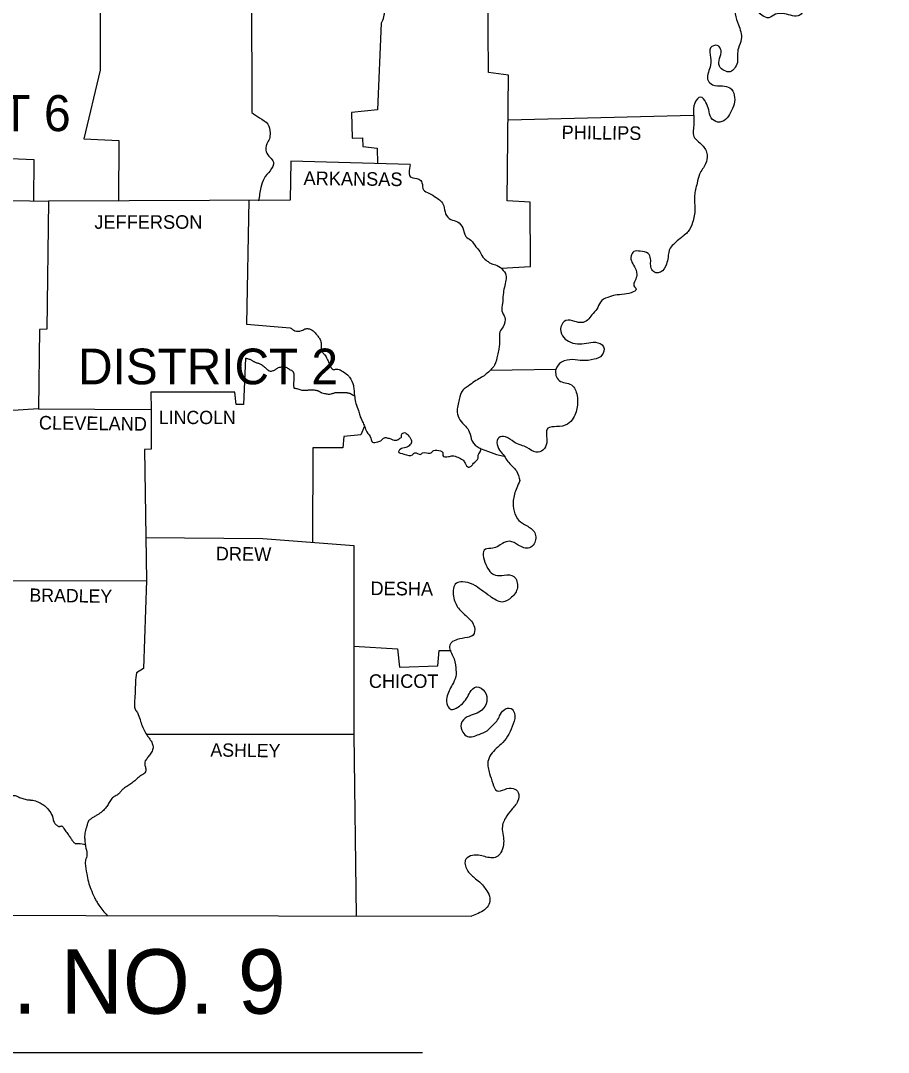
# Model space of a CAD drawing. Extents: x 0 to 3171, y 0 to 2059.
# Drawn here: x 2812.1 to 3086.8, y 1309.2 to 1635.7 of the extents above; entities that cross this region are included whole.
import ezdxf

# ---------------------------------------------------------------- set-up
doc = ezdxf.new("R2010")
doc.units = 0
doc.layers.add('Default', color=7, linetype='Continuous')
doc.layers.add('Level 1', color=7, linetype='Continuous')

msp = doc.modelspace()

# ---------------------------------------------------------------- linework, layer by layer
at = {"layer": 'Default'}
msp.add_line((2620.8, 1309.22), (2939.39, 1309.22), dxfattribs=at)
at = {"layer": 'Level 1'}
msp.add_line((2960.87, 1525.15), (2981.61, 1525.46), dxfattribs=at)
for points in [[(2870.87, 1663.24), (2871.07, 1645.34), (2885.17, 1645.04), (2885.27, 1606.64)], [(2831.37, 1658.64), (2837.17, 1658.24), (2837.27, 1620.04), (2832.07, 1598.34), (2843.17, 1597.84), (2843.07, 1578.73)], [(2964.24, 1557.34), (2973.57, 1557.94), (2973.47, 1578.24), (2966.17, 1578.74), (2966.57, 1618.44), (2960.27, 1619.34), (2960.07, 1646.04), (3045.85, 1646.64)], [(2753.47, 1633.68), (2765.37, 1632.94), (2764.97, 1620.44), (2778.07, 1619.94), (2778.27, 1609.04), (2784.47, 1608.54), (2784.47, 1606.64), (2790.27, 1606.24), (2790.47, 1599.24), (2803.67, 1599.24), (2804.07, 1592.34), (2816.27, 1591.74), (2816.17, 1578.72)], [(2926.27, 1634.94), (2925.07, 1607.54), (2916.87, 1606.64), (2917.07, 1598.54), (2920.37, 1598.64), (2920.47, 1595.84), (2924.97, 1595.34), (2925.12, 1590.51)], [(2966.43, 1604.33), (3025.18, 1605.79)], [(2935.47, 1590.24), (2897.67, 1591.24), (2897.47, 1578.94), (2820.97, 1578.64)], [(2763.37, 1565.44), (2768.97, 1566.24), (2769.37, 1569.64), (2772.67, 1570.24), (2772.87, 1572.24), (2796.17, 1572.94), (2797.07, 1579.04), (2820.97, 1578.64)], [(2820.97, 1578.64), (2820.37, 1538.04), (2818.07, 1537.94), (2817.77, 1512.84)], [(2884.4, 1578.89), (2883.57, 1539.64), (2897.47, 1538.54)], [(2883.27, 1528.94), (2882.67, 1514.24), (2880.37, 1514.24), (2879.97, 1518.14), (2853.37, 1518.14), (2853.4, 1512.64)], [(2817.77, 1512.84), (2803.15, 1511.94)], [(2817.77, 1512.84), (2853.4, 1512.64)], [(2853.4, 1512.64), (2853.47, 1500.14), (2851.37, 1500.04), (2851.97, 1458.54)], [(2920.97, 1507.34), (2919.77, 1504.64), (2914.47, 1504.14), (2914.17, 1500.54), (2904.67, 1500.54), (2904.57, 1470.64)], [(2957.97, 1500.24), (2960.21, 1499.37), (2962.77, 1498.47), (2965.21, 1497.85)], [(2851.67, 1472.14), (2888.77, 1471.84), (2917.57, 1469.64)], [(2917.57, 1469.64), (2917.57, 1409.85), (2918.37, 1352.41)], [(2806.77, 1458.44), (2851.97, 1458.54)], [(2851.97, 1458.54), (2850.97, 1430.74), (2848.77, 1429.34)], [(2917.57, 1437.77), (2931.47, 1436.94), (2932.07, 1431.14), (2944.17, 1431.54), (2944.67, 1436.44), (2948.41, 1436.44)], [(2588.17, 1433.84), (2588.37, 1352.95), (2954.87, 1352.35)], [(2851.92, 1409.95), (2917.57, 1409.95)]]:
    msp.add_lwpolyline(points, dxfattribs=at)
for points in [[(3082.47, 1721.54), (3082.87, 1718.64), (3081.17, 1715.54), (3080.57, 1712.44), (3080.87, 1709.34), (3077.67, 1707.64), (3074.87, 1705.64), (3076.47, 1703.24), (3079.47, 1701.04), (3082.47, 1699.34), (3084.37, 1697.64), (3084.87, 1693.54), (3085.37, 1690.94), (3086.37, 1687.34), (3086.77, 1684.84), (3084.97, 1681.84), (3082.87, 1681.24), (3080.67, 1681.94), (3078.07, 1682.14), (3075.97, 1680.14), (3074.47, 1677.34), (3072.97, 1674.54), (3071.87, 1672.14), (3070.77, 1669.54), (3068.57, 1666.54), (3065.87, 1666.04), (3062.67, 1665.24), (3060.77, 1663.04), (3061.07, 1659.34), (3062.87, 1656.84), (3064.27, 1653.74), (3065.27, 1651.04), (3064.77, 1647.64), (3063.37, 1645.14), (3061.57, 1643.64), (3060.77, 1640.44), (3059.47, 1638.04), (3058.27, 1637.24), (3055.87, 1637.44), (3053.27, 1637.94), (3051.07, 1637.74), (3048.97, 1636.64), (3046.87, 1637.34), (3044.67, 1639.74), (3042.87, 1641.54), (3040.87, 1642.24), (3038.77, 1641.14), (3038.37, 1637.84), (3039.37, 1634.44), (3040.27, 1629.84), (3039.37, 1627.04), (3039.07, 1622.44)], [(2925.17, 1644.54), (2925.05, 1644.3), (2924.96, 1644.05), (2924.83, 1643.54), (2924.77, 1643.04), (2924.76, 1642.79), (2924.77, 1642.54), (2924.85, 1642), (2925.02, 1641.47), (2925.27, 1640.95), (2925.41, 1640.69), (2925.57, 1640.44), (2925.71, 1640.3), (2925.89, 1640.2), (2926.3, 1640.1), (2926.7, 1640), (2926.86, 1639.9), (2926.92, 1639.83), (2926.97, 1639.74), (2927.02, 1639.62), (2927.06, 1639.49), (2927.22, 1638.74), (2927.23, 1638.24), (2927.21, 1637.99), (2927.17, 1637.74), (2926.97, 1636.73), (2926.84, 1636.23), (2926.76, 1635.99), (2926.67, 1635.74), (2926.49, 1635.33), (2926.27, 1634.94)], [(3039.07, 1622.44), (3036.77, 1619.54), (3033.37, 1621.34), (3033.37, 1623.74), (3033.87, 1626.24), (3032.67, 1627.84), (3030.57, 1627.14), (3030.57, 1624.04), (3030.37, 1621.04), (3029.77, 1616.74), (3031.17, 1615.44), (3034.37, 1615.04), (3036.67, 1614.44), (3038.07, 1612.14), (3037.97, 1609.34), (3036.87, 1606.64), (3035.27, 1604.44), (3032.77, 1603.64), (3030.77, 1604.94), (3029.97, 1607.54), (3029.07, 1609.84), (3027.37, 1611.54), (3025.57, 1609.64), (3025.17, 1606.14), (3025.27, 1603.14), (3025.27, 1599.04), (3027.87, 1596.34), (3029.47, 1593.24), (3028.97, 1590.44), (3027.07, 1587.14), (3026.27, 1584.24), (3025.47, 1580.34), (3025.57, 1576.04), (3024.87, 1571.84), (3023.47, 1569.04), (3020.87, 1566.74), (3019.17, 1565.24), (3017.77, 1563.74), (3017.07, 1560.74), (3016.57, 1558.64), (3014.67, 1556.14), (3013.17, 1555.94), (3011.97, 1556.94), (3011.57, 1558.64), (3011.57, 1560.34), (3010.77, 1562.04), (3008.27, 1562.74), (3006.27, 1562.64), (3005.37, 1561.24), (3006.67, 1557.34), (3007.17, 1554.84), (3006.47, 1551.44), (3006.87, 1551.04), (3003.27, 1549.14), (3000.37, 1548.84), (2997.97, 1548.14), (2995.67, 1546.64), (2994.57, 1544.44), (2992.97, 1542.64), (2991.57, 1540.94), (2989.67, 1540.14), (2987.57, 1540.54), (2984.77, 1540.84), (2983.17, 1538.84), (2983.67, 1535.94), (2985.57, 1534.24), (2988.37, 1533.44), (2991.27, 1533.64), (2994.07, 1533.94), (2996.67, 1532.54), (2996.17, 1529.84), (2993.67, 1528.54), (2989.97, 1528.14), (2986.97, 1528.44), (2983.37, 1527.64), (2981.57, 1525.34), (2982.57, 1521.84), (2986.47, 1520.44), (2988.27, 1517.14), (2988.37, 1514.04), (2987.07, 1509.94), (2985.27, 1508.04), (2981.77, 1507.24), (2979.07, 1506.74), (2978.67, 1502.14), (2977.47, 1499.84), (2975.37, 1499.14), (2972.37, 1500.64), (2970.57, 1501.34), (2968.37, 1502.34), (2965.57, 1504.04), (2963.47, 1503.74), (2964.07, 1499.34), (2964.27, 1499.14), (2966.67, 1495.84), (2969.07, 1493.24), (2970.17, 1490.14)], [(2885.27, 1606.64), (2887.77, 1604.94), (2890.37, 1602.94), (2891.07, 1600.24), (2890.87, 1598.34), (2890.07, 1596.74), (2889.87, 1594.24), (2891.07, 1592.44), (2892.17, 1590.94), (2891.07, 1588.24), (2889.17, 1585.74), (2888.17, 1582.94), (2887.47, 1578.74)], [(2935.47, 1590.24), (2935.77, 1586.14), (2938.17, 1585.54), (2939.17, 1584.44), (2939.67, 1582.14), (2941.37, 1581.14), (2943.67, 1579.74), (2945.07, 1578.74), (2946.07, 1577.14), (2946.67, 1574.54), (2948.27, 1572.84), (2950.47, 1572.04), (2952.07, 1570.14), (2953.07, 1567.44), (2954.67, 1566.24), (2956.27, 1564.14), (2957.07, 1563.24), (2958.47, 1560.84), (2959.87, 1559.64), (2960.87, 1558.94), (2962.47, 1558.44), (2964.47, 1557.14), (2965.77, 1555.14), (2965.77, 1553.64), (2965.27, 1551.34), (2964.87, 1548.94), (2964.67, 1546.24), (2964.47, 1543.84), (2965.37, 1541.84), (2964.87, 1538.84), (2963.87, 1537.24), (2963.77, 1535.04), (2963.47, 1531.74), (2963.07, 1529.84), (2962.17, 1526.74), (2960.87, 1525.14)], [(2897.47, 1538.54), (2898.97, 1537.54), (2901.07, 1537.64), (2902.47, 1538.24), (2903.57, 1538.14), (2905.07, 1537.24), (2906.07, 1536.04), (2906.77, 1535.14), (2907.27, 1533.74), (2907.27, 1532.44), (2907.77, 1530.64), (2908.37, 1529.94), (2909.17, 1528.64), (2909.67, 1527.44), (2909.97, 1526.64), (2911.07, 1525.34), (2912.07, 1525.44), (2912.97, 1525.34), (2914.17, 1524.64), (2915.97, 1523.24), (2916.27, 1522.84), (2917.47, 1520.24), (2917.67, 1518.64), (2917.87, 1516.54), (2918.27, 1514.54), (2919.07, 1512.34), (2919.47, 1510.84), (2920.37, 1508.74), (2920.97, 1507.34), (2921.77, 1505.54), (2922.97, 1503.54), (2923.47, 1502.34), (2925.17, 1502.44), (2926.37, 1502.94), (2927.27, 1503.74), (2928.37, 1503.64), (2929.57, 1503.24), (2931.17, 1502.94), (2932.17, 1503.54), (2932.67, 1503.94), (2932.77, 1504.84), (2933.67, 1505.34), (2934.67, 1504.64), (2935.77, 1503.04), (2935.77, 1502.04), (2935.37, 1501.44), (2934.07, 1500.64), (2932.27, 1500.04), (2931.77, 1499.34), (2933.47, 1498.54), (2936.17, 1498.34), (2936.87, 1498.94), (2938.67, 1498.44), (2939.37, 1498.94), (2941.77, 1498.84), (2942.87, 1499.64), (2945.07, 1499.54), (2945.77, 1499.04), (2945.77, 1498.14), (2947.57, 1497.74), (2948.87, 1498.04), (2950.57, 1497.54), (2952.07, 1496.74), (2952.87, 1495.64), (2953.87, 1494.44), (2954.77, 1494.74), (2955.47, 1495.64), (2956.97, 1497.24), (2956.97, 1498.24), (2957.37, 1498.94), (2957.97, 1500.24)], [(2883.27, 1528.94), (2883.73, 1528.85), (2884.19, 1528.71), (2885.07, 1528.34), (2885.4, 1528.17), (2885.72, 1527.99), (2886.04, 1527.81), (2886.37, 1527.64), (2886.79, 1527.48), (2887.23, 1527.36), (2887.66, 1527.23), (2888.07, 1527.04), (2888.63, 1526.66), (2889.17, 1526.24), (2889.55, 1525.92), (2889.91, 1525.58), (2890.28, 1525.24), (2890.47, 1525.09), (2890.67, 1524.94), (2891.08, 1524.8), (2891.55, 1524.83), (2892.03, 1524.97), (2892.47, 1525.14), (2892.8, 1525.33), (2893.1, 1525.56), (2893.42, 1525.78), (2893.77, 1525.94), (2895.07, 1526.14), (2896.07, 1526.04), (2897.17, 1525.44), (2897.82, 1525.07), (2898.12, 1524.85), (2898.25, 1524.71), (2898.31, 1524.63), (2898.37, 1524.54), (2898.57, 1523.9), (2898.57, 1523.57), (2898.57, 1523.24), (2898.57, 1521.74), (2898.57, 1519.64), (2898.64, 1519.5), (2898.83, 1519.42), (2899.27, 1519.34), (2900.51, 1518.96), (2901.77, 1518.74), (2902.19, 1518.75), (2902.62, 1518.78), (2903.04, 1518.82), (2903.47, 1518.84), (2904.27, 1518.86), (2905.07, 1518.84), (2905.73, 1518.74), (2906.05, 1518.65), (2906.37, 1518.54), (2906.65, 1518.4), (2906.92, 1518.23), (2907.19, 1518.07), (2907.47, 1517.94), (2908.27, 1517.74), (2909.47, 1517.54), (2910.47, 1517.64), (2910.9, 1517.75), (2911.32, 1517.88), (2911.74, 1517.99), (2912.17, 1518.04), (2913.17, 1518.04), (2914.77, 1518.04), (2915.27, 1518.01), (2915.52, 1517.98), (2915.77, 1517.94), (2916.84, 1517.55), (2917.35, 1517.24), (2917.83, 1516.91)], [(2960.87, 1525.14), (2958.07, 1522.84), (2956.27, 1521.84), (2954.37, 1520.44), (2952.07, 1518.74), (2950.97, 1515.84), (2950.37, 1511.84), (2951.17, 1509.44), (2952.97, 1507.34), (2954.17, 1505.64), (2955.07, 1502.64), (2957.27, 1500.54), (2957.97, 1500.24)], [(2970.17, 1490.14), (2969.17, 1487.84), (2968.07, 1483.84), (2968.37, 1480.44), (2969.87, 1477.54), (2972.27, 1475.94), (2974.87, 1473.64), (2974.67, 1470.14), (2973.17, 1468.84), (2969.67, 1469.74), (2966.97, 1470.94), (2964.67, 1470.24), (2961.57, 1468.74), (2959.27, 1468.44), (2959.37, 1463.64), (2962.47, 1460.24), (2965.17, 1460.24), (2968.27, 1459.84), (2969.37, 1456.24), (2967.57, 1453.24), (2964.57, 1451.74), (2960.77, 1453.54), (2958.07, 1455.44), (2955.37, 1457.24), (2951.97, 1458.14), (2950.07, 1457.74), (2949.17, 1453.54), (2950.77, 1449.74), (2953.37, 1447.14), (2955.77, 1443.74), (2955.37, 1441.24), (2953.57, 1440.54), (2950.37, 1439.84), (2948.47, 1438.84), (2947.97, 1438.04), (2948.97, 1434.64), (2949.87, 1430.94), (2949.87, 1428.15), (2948.77, 1425.55), (2947.07, 1421.55), (2947.27, 1418.95), (2948.47, 1417.75), (2949.97, 1418.15), (2951.97, 1419.55), (2953.27, 1421.15), (2954.37, 1423.15), (2956.47, 1424.85), (2959.07, 1423.35), (2959.67, 1420.25), (2958.17, 1417.55), (2956.07, 1416.35), (2953.47, 1415.35), (2951.57, 1413.15), (2952.07, 1410.55), (2953.57, 1409.15), (2957.27, 1409.85), (2959.77, 1410.95), (2961.17, 1412.35), (2962.87, 1414.05), (2963.77, 1415.75), (2965.07, 1417.55), (2967.37, 1418.05), (2968.47, 1416.55), (2968.07, 1413.15), (2966.67, 1409.95), (2964.77, 1407.25), (2962.67, 1405.35), (2960.07, 1401.25), (2960.57, 1397.45), (2961.57, 1394.35), (2962.97, 1391.95), (2965.37, 1392.45), (2968.07, 1392.75), (2969.67, 1391.45), (2969.47, 1388.65), (2967.47, 1385.95), (2965.57, 1383.35), (2964.57, 1379.75), (2964.97, 1377.25), (2964.97, 1374.95), (2964.17, 1372.45), (2962.77, 1371.05), (2959.07, 1371.15), (2955.17, 1371.55), (2953.07, 1370.35), (2953.47, 1366.95), (2955.77, 1364.45), (2957.37, 1363.15), (2959.67, 1360.35), (2960.67, 1358.05), (2960.37, 1356.05), (2958.97, 1354.35), (2954.87, 1352.35)], [(2848.77, 1429.34), (2848.47, 1426.25), (2848.37, 1423.35), (2848.17, 1420.55), (2848.11, 1419.49), (2848.12, 1418.97), (2848.17, 1418.45), (2848.37, 1417.84), (2848.71, 1417.28), (2849.08, 1416.73), (2849.37, 1416.15), (2850.07, 1413.95), (2850.77, 1412.05), (2852.17, 1409.55), (2852.48, 1409.06), (2852.82, 1408.6), (2853.15, 1408.13), (2853.47, 1407.65), (2853.98, 1406.3), (2854.02, 1405.6), (2853.87, 1404.95), (2853.07, 1403.55), (2852.7, 1403.01), (2852.32, 1402.49), (2851.93, 1401.97), (2851.57, 1401.45), (2851.4, 1400.53), (2851.62, 1399.49), (2851.78, 1398.47), (2851.47, 1397.65), (2851.26, 1397.47), (2851.04, 1397.31), (2850.58, 1397.03), (2850.11, 1396.76), (2849.67, 1396.45), (2848.54, 1395.43), (2847.97, 1394.92), (2847.37, 1394.45), (2846.07, 1393.55), (2844.67, 1392.65), (2844.26, 1392.29), (2843.9, 1391.87), (2843.55, 1391.44), (2843.17, 1391.05), (2842.64, 1390.65), (2842.05, 1390.32), (2841.48, 1389.97), (2840.97, 1389.55), (2840.52, 1388.96), (2840.15, 1388.31), (2839.79, 1387.66), (2839.37, 1387.05), (2838.95, 1386.54), (2838.53, 1386.04), (2837.57, 1385.15), (2836.07, 1384.15), (2835.55, 1383.83), (2835.01, 1383.52), (2834.22, 1383.03), (2833.97, 1382.85), (2833.61, 1382.44), (2833.37, 1381.94), (2833.07, 1380.85), (2832.8, 1379.92), (2832.56, 1379), (2832.4, 1378.08), (2832.37, 1377.15), (2832.49, 1375.79), (2832.67, 1374.45), (2833.07, 1372.05), (2833.02, 1371.3), (2832.82, 1370.55), (2832.61, 1369.8), (2832.57, 1369.05), (2833.07, 1365.75), (2833.57, 1363.15), (2834.37, 1360.85), (2835.47, 1358.25), (2836.12, 1357.02), (2836.87, 1355.85), (2838.12, 1354.14), (2839.5, 1352.54)], [(2749.07, 1406.25), (2750.67, 1407.35), (2752.17, 1407.95), (2752.92, 1407.82), (2753.29, 1407.72), (2753.67, 1407.65), (2755.27, 1407.45), (2755.62, 1407.46), (2755.97, 1407.53), (2756.32, 1407.61), (2756.67, 1407.65), (2758.47, 1407.35), (2758.87, 1407.14), (2759.24, 1406.9), (2759.59, 1406.66), (2759.97, 1406.45), (2760.8, 1405.99), (2761.67, 1405.75), (2763.37, 1405.75), (2764.87, 1405.75), (2765.23, 1405.62), (2765.53, 1405.33), (2765.83, 1405.03), (2766.17, 1404.85), (2766.76, 1404.76), (2767.37, 1404.74), (2767.98, 1404.8), (2768.57, 1404.95), (2769.07, 1405.14), (2769.57, 1405.35), (2770.07, 1405.56), (2770.57, 1405.75), (2772.57, 1406.35), (2773.24, 1406.55), (2773.94, 1406.73), (2774.62, 1406.79), (2774.95, 1406.75), (2775.27, 1406.65), (2776.52, 1405.88), (2777.67, 1404.95), (2778.53, 1404.26), (2779.37, 1403.55), (2780.77, 1401.95), (2781.04, 1401.51), (2781.27, 1401.05), (2781.5, 1400.59), (2781.77, 1400.15), (2782.87, 1399.15), (2783.31, 1398.92), (2783.75, 1398.73), (2784.67, 1398.45), (2786.07, 1398.15), (2787.77, 1397.65), (2788.25, 1397.51), (2788.48, 1397.41), (2788.67, 1397.25), (2788.95, 1396.8), (2789.14, 1396.32), (2789.29, 1395.83), (2789.47, 1395.35), (2789.61, 1395.02), (2789.72, 1394.69), (2789.95, 1394.03), (2790.26, 1393.39), (2790.49, 1393.06), (2790.62, 1392.91), (2790.77, 1392.75), (2791.37, 1392.25), (2792, 1391.92), (2792.64, 1391.78), (2793.27, 1391.85), (2794.04, 1392.11), (2794.82, 1392.44), (2795.59, 1392.77), (2796.37, 1393.05), (2798.87, 1393.75), (2800.67, 1394.35), (2801.77, 1394.75), (2802.01, 1394.79), (2802.27, 1394.8), (2802.52, 1394.8), (2802.77, 1394.85), (2802.79, 1394.86), (2802.76, 1394.88), (2802.63, 1394.94), (2802.49, 1395), (2802.46, 1395.02), (2802.47, 1395.05), (2802.75, 1395.18), (2803.07, 1395.3), (2803.67, 1395.35), (2803.96, 1395.23), (2804.26, 1395.05), (2804.77, 1394.55), (2804.96, 1394.27), (2805.12, 1393.99), (2805.29, 1393.71), (2805.47, 1393.45), (2806.67, 1391.85), (2807.19, 1391.14), (2807.47, 1390.79), (2807.77, 1390.45), (2808.01, 1390.24), (2808.3, 1390.1), (2808.59, 1390), (2808.87, 1389.95), (2809.14, 1390.03), (2809.41, 1390.27), (2809.69, 1390.49), (2809.97, 1390.55), (2811.47, 1390.05), (2812.77, 1389.55), (2814.27, 1389.15), (2814.59, 1389.11), (2814.92, 1389.09), (2815.25, 1389.08), (2815.57, 1389.05), (2817.27, 1388.65), (2818.57, 1387.95), (2819.77, 1387.25), (2820.97, 1385.95), (2822.17, 1383.95), (2822.3, 1383.56), (2822.37, 1383.16), (2822.44, 1382.75), (2822.57, 1382.35), (2823.16, 1381.45), (2823.55, 1381.08), (2823.97, 1380.75), (2824.29, 1380.69), (2824.66, 1380.78), (2825.01, 1380.86), (2825.27, 1380.75), (2825.76, 1380.1), (2826.23, 1379.46), (2827.17, 1378.15), (2827.87, 1377.15), (2828.52, 1376.18), (2828.89, 1375.74), (2829.12, 1375.53), (2829.37, 1375.35), (2829.63, 1375.26), (2829.91, 1375.29), (2830.19, 1375.34), (2830.47, 1375.35), (2832.6, 1374.94)]]:
    msp.add_spline(points, degree=3, dxfattribs=at)

# ---------------------------------------------------------------- texts
at = {"layer": 'Default'}
msp.add_text('  ARK. HWY. DIST. NO. 9', height=20.4, dxfattribs=at).set_placement((2582.28, 1321.44))
at = {"layer": 'Level 1'}
for s, height, p in [('DISTRICT 6', 11.4, (2744.97, 1600.74)), ('JEFFERSON', 4.3, (2835.47, 1569.84)), ('DISTRICT 2', 11.299, (2830.31, 1520.63)), ('LINCOLN', 4.2, (2855.87, 1508.04)), ('CHICOT', 4.3, (2922.37, 1424.55))]:
    msp.add_text(s, height=height, dxfattribs=at).set_placement(p)
for s, height, rotation, p in [('PHILLIPS', 4.299, 359.318, (2983.37, 1598.24)), ('ARKANSAS', 4.299, 359.2678, (2901.67, 1583.74)), ('CLEVELAND', 4.301, 359.3377, (2817.87, 1506.34)), ('DREW', 4.299, 359.2258, (2873.87, 1464.94)), ('DESHA', 4.299, 359.3704, (2922.87, 1453.94)), ('BRADLEY', 4.199, 359.1449, (2814.87, 1451.84)), ('ASHLEY', 4.2, 359.2361, (2872.17, 1402.85))]:
    msp.add_text(s, height=height, rotation=rotation, dxfattribs=at).set_placement(p)

doc.saveas('drawing.dxf')
